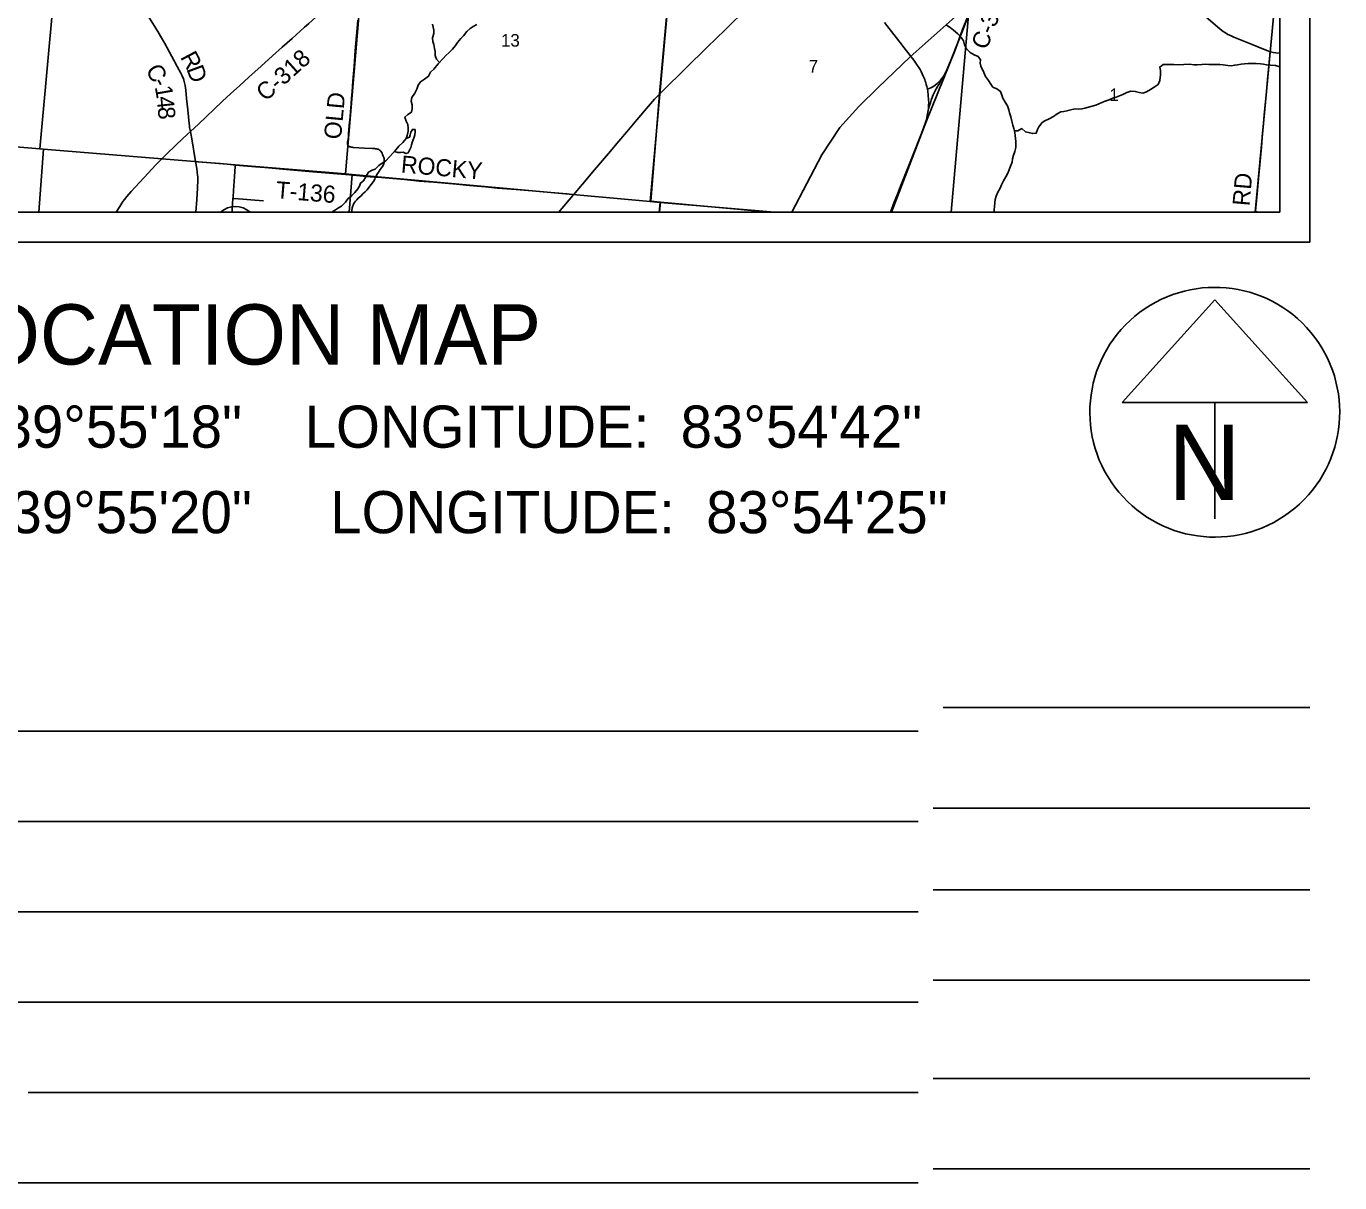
# Model space of a CAD drawing. Extents: x 0 to 34, y 0 to 22.
# Drawn here: x 4.739 to 9.099, y 10.877 to 14.717 of the extents above; entities that cross this region are included whole.
import ezdxf

# ---------------------------------------------------------------- set-up
doc = ezdxf.new("R2010")
doc.units = 0
for name, color, linetype in [('Default', 7, 'Continuous'), ('GM_X_City_Street', 7, 'Continuous'), ('GM_X_County_Road', 7, 'Continuous'), ('GM_X_County_Road_Text', 7, 'Continuous'), ('GM_X_Major_River_Text', 7, 'Continuous'), ('GM_X_Minor_Lake', 7, 'Continuous'), ('GM_X_Minor_River', 7, 'Continuous'), ('GM_X_Rail_Line', 7, 'Continuous'), ('GM_X_Section', 7, 'Continuous'), ('GM_X_Section_Text', 7, 'Continuous'), ('GM_X_Township_Road', 7, 'Continuous'), ('GM_X_Township_Road_Text', 7, 'Continuous'), ('GM_X_US_Route', 7, 'Continuous'), ('SH_Data', 7, 'Continuous'), ('SH_Text', 7, 'Continuous')]:
    doc.layers.add(name, color=color, linetype=linetype)

msp = doc.modelspace()

# ---------------------------------------------------------------- linework, layer by layer
at = {"layer": 'Default'}
for points in [[(7.2235, 14.1), (7.8093, 14.1), (7.893, 15.0559), (6.9002, 15.1449), (6.8099, 14.1356), (6.8432, 14.1321)], [(7.8093, 14.1), (8.8187, 14.1), (8.8988, 14.9496), (7.893, 15.0559)], [(8.8187, 14.1), (8.9, 14.1), (8.9, 14.9495), (8.8988, 14.9496)], [(3.7756, 14.1), (4.7807, 14.1), (4.7952, 14.3092), (4.7835, 14.3098), (3.8021, 14.3916)], [(4.7807, 14.1), (5.8111, 14.1), (5.8205, 14.2252), (5.7982, 14.227), (4.7952, 14.3092)], [(5.8111, 14.1), (6.8403, 14.1), (6.8432, 14.1321), (6.8099, 14.1356), (5.8205, 14.2252)], [(6.8403, 14.1), (7.2235, 14.1), (6.8432, 14.1321)]]:
    msp.add_lwpolyline(points, close=True, dxfattribs=at)
at = {"layer": 'GM_X_City_Street'}
for points in [[(6.9742, 15.9512), (6.8413, 14.4929), (6.8121, 14.1362), (6.8442, 14.1329), (7.2075, 14.1), (8.9, 14.1), (8.9, 20.0308)], [(2.1, 15.6775), (2.1, 14.1), (6.8413, 14.1), (6.8442, 14.1329), (6.8121, 14.1362), (6.8413, 14.4929), (6.9742, 15.9512)]]:
    msp.add_lwpolyline(points, dxfattribs=at)
msp.add_lwpolyline([(6.8413, 14.1), (7.2075, 14.1), (6.8442, 14.1329)], close=True, dxfattribs=at)
at = {"layer": 'GM_X_County_Road'}
msp.add_line((8.8195, 14.1), (8.8197, 14.1018), dxfattribs=at)
for points in [[(7.7781, 14.5434), (7.7795, 14.5452), (7.7848, 14.5528), (7.7895, 14.5608), (7.7937, 14.569), (7.7987, 14.5803), (7.8089, 14.6063), (7.8301, 14.6601), (7.8465, 14.702), (7.8702, 14.7628), (7.8835, 14.7975), (7.8982, 14.8352), (7.9084, 14.8612), (7.9276, 14.9103), (7.9492, 14.9652), (7.9593, 14.9913), (7.9806, 15.0463), (7.997, 15.0885)], [(5.2834, 14.3675), (5.3102, 14.3924), (5.3892, 14.4668), (5.4048, 14.4812), (5.4275, 14.5022), (5.4459, 14.519), (5.4779, 14.5483), (5.5181, 14.585), (5.5561, 14.6191), (5.5885, 14.6481), (5.6209, 14.6768), (5.6627, 14.7139), (5.6765, 14.7264), (5.6996, 14.7472), (5.7203, 14.766), (5.7783, 14.8176), (5.8131, 14.8486), (5.8434, 14.8753), (5.8549, 14.8856)], [(6.8408, 14.4917), (6.8415, 14.4924), (6.8505, 14.5014), (6.9283, 14.5774), (6.9993, 14.6471), (7.0594, 14.7056), (7.0838, 14.7296), (7.1082, 14.7535), (7.1173, 14.7619), (7.1221, 14.7656), (7.1247, 14.7672), (7.1302, 14.77), (7.1359, 14.7723), (7.1446, 14.7755), (7.1653, 14.7821), (7.192, 14.7905), (7.248, 14.8091), (7.3424, 14.8403), (7.3747, 14.8516), (7.4009, 14.8614), (7.4386, 14.8764)], [(5.2834, 14.3675), (5.2817, 14.3768), (5.2809, 14.3811), (5.2799, 14.387), (5.2791, 14.3933), (5.2745, 14.4397), (5.2709, 14.4768), (5.268, 14.5046), (5.2659, 14.5201), (5.2641, 14.5293), (5.2617, 14.5383), (5.2601, 14.5434), (5.2586, 14.5472), (5.2561, 14.553), (5.252, 14.5613), (5.24, 14.5832), (5.2296, 14.6022), (5.1983, 14.6594), (5.1845, 14.6838), (5.175, 14.6998), (5.1587, 14.7263), (5.1425, 14.7528), (5.1216, 14.7873), (5.1201, 14.7896)], [(8.6313, 14.7682), (8.7025, 14.7079), (8.7123, 14.7002), (8.7201, 14.6949), (8.7282, 14.6902), (8.7366, 14.6861), (8.7481, 14.6811), (8.8087, 14.6567), (8.8459, 14.6411), (8.8604, 14.6354), (8.8666, 14.6333), (8.8693, 14.6326)], [(8.8197, 14.1018), (8.8211, 14.1152), (8.8242, 14.1493), (8.8264, 14.1741), (8.8273, 14.1865), (8.8282, 14.1988), (8.8305, 14.2236), (8.8317, 14.236), (8.8326, 14.2452), (8.8347, 14.2691), (8.838, 14.3048), (8.8402, 14.3295), (8.8423, 14.3512), (8.8464, 14.3946), (8.849, 14.4224), (8.8529, 14.4658), (8.8559, 14.4998), (8.8594, 14.5401), (8.8626, 14.5741), (8.8672, 14.6209), (8.8677, 14.6249), (8.8681, 14.6281), (8.8693, 14.6326)], [(8.8693, 14.6326), (8.8737, 14.6314), (8.8785, 14.6303), (8.8877, 14.6288), (8.9, 14.6272)], [(7.7305, 14.508), (7.7362, 14.5101), (7.742, 14.5127), (7.7481, 14.516), (7.7556, 14.5214), (7.7628, 14.5272), (7.7695, 14.5335), (7.7737, 14.538), (7.7781, 14.5434)], [(7.7337, 14.4429), (7.7374, 14.4537), (7.7402, 14.4624), (7.743, 14.4718), (7.747, 14.4836), (7.7495, 14.4899), (7.7514, 14.4943), (7.7545, 14.5002), (7.76, 14.5094), (7.7715, 14.5295), (7.7743, 14.5351), (7.7781, 14.5434)], [(6.5556, 14.1575), (6.5853, 14.1927), (6.6254, 14.2402), (6.6714, 14.295), (6.7057, 14.3351), (6.7378, 14.3731), (6.7659, 14.4063), (6.8042, 14.4512), (6.8246, 14.4747), (6.8352, 14.486), (6.8408, 14.4917)], [(5.0372, 14.1), (5.0488, 14.1188), (5.0588, 14.1346), (5.0643, 14.1422), (5.0723, 14.1518), (5.0868, 14.1679), (5.1436, 14.2297), (5.1688, 14.2572), (5.1839, 14.2729), (5.2017, 14.2902), (5.2378, 14.3244), (5.2738, 14.3586), (5.2834, 14.3675)], [(5.3005, 14.268), (5.2879, 14.3429), (5.2847, 14.3607), (5.2834, 14.3675)], [(5.302, 14.1), (5.3046, 14.1416), (5.3066, 14.1789), (5.3077, 14.2069), (5.3076, 14.2163), (5.3062, 14.2318), (5.3045, 14.2442), (5.3005, 14.268)], [(6.5072, 14.1), (6.5112, 14.1048), (6.5533, 14.1547), (6.5556, 14.1575)]]:
    msp.add_lwpolyline(points, dxfattribs=at)
at = {"layer": 'GM_X_Major_River_Text'}
msp.add_line((5.3836, 14.1), (5.4815, 14.1), dxfattribs=at)
msp.add_arc((5.4326, 14.0439), 0.0744, 48.835, 131.165, dxfattribs=at)
at = {"layer": 'GM_X_Minor_Lake'}
for points in [[(5.9607, 14.3015), (5.9719, 14.298), (5.981, 14.2983), (5.9897, 14.2989), (5.9984, 14.295), (6.0059, 14.2972), (6.0106, 14.3058), (6.0148, 14.3141), (6.0172, 14.3232), (6.02, 14.3315), (6.0231, 14.3398), (6.0262, 14.3489), (6.0282, 14.3568), (6.0298, 14.3662), (6.0292, 14.3742), (6.0205, 14.3743), (6.0151, 14.3653), (6.0127, 14.3562), (6.0111, 14.3487), (5.9993, 14.3443)], [(5.9993, 14.3443), (5.9886, 14.3307), (5.9752, 14.3188), (5.9607, 14.3015)]]:
    msp.add_lwpolyline(points, dxfattribs=at)
at = {"layer": 'GM_X_Minor_River'}
for points in [[(6.1103, 14.5966), (6.1009, 14.6076), (6.0965, 14.6205), (6.0959, 14.6334), (6.0942, 14.6433), (6.0917, 14.6566), (6.0887, 14.6665), (6.087, 14.6791), (6.0913, 14.6927), (6.0922, 14.7045), (6.0897, 14.7144), (6.0868, 14.7239)], [(6.106, 14.5919), (6.1223, 14.6096), (6.1315, 14.6202), (6.141, 14.6292), (6.1532, 14.6405), (6.1639, 14.6537), (6.1704, 14.6635), (6.1811, 14.6767), (6.1906, 14.685), (6.2013, 14.6993), (6.2124, 14.7094), (6.2219, 14.7158), (6.234, 14.7233)], [(7.7933, 14.7202), (7.8054, 14.7125), (7.8174, 14.7041), (7.8309, 14.6922), (7.8426, 14.68), (7.8497, 14.6686), (7.853, 14.6553), (7.8601, 14.642), (7.8728, 14.6301), (7.8856, 14.622), (7.8985, 14.617), (7.9071, 14.606), (7.9059, 14.595), (7.9077, 14.5851), (7.9177, 14.564)], [(6.0478, 14.5324), (6.0607, 14.5413), (6.0741, 14.551), (6.0807, 14.5642), (6.0914, 14.575), (6.106, 14.5919)], [(8.5048, 14.5554), (8.5041, 14.5697), (8.5016, 14.5815), (8.513, 14.5901), (8.5485, 14.5898), (8.5637, 14.5886), (8.5815, 14.59), (8.5989, 14.5913), (8.6159, 14.5889), (8.6261, 14.5885), (8.6412, 14.5899), (8.6541, 14.5913), (8.6651, 14.5905), (8.6756, 14.5896), (8.6893, 14.5899), (8.7018, 14.5906), (8.7127, 14.589), (8.7275, 14.5866), (8.7403, 14.5861), (8.7502, 14.5875), (8.7604, 14.5894), (8.7721, 14.5912), (8.7827, 14.5918), (8.7952, 14.5929), (8.81, 14.5931), (8.8217, 14.5931), (8.8364, 14.5926), (8.8466, 14.591), (8.8565, 14.589), (8.8693, 14.5874), (8.8856, 14.5869), (8.8973, 14.583), (8.9, 14.5818)], [(5.7528, 14.1), (5.7621, 14.1058), (5.7754, 14.1143), (5.7849, 14.1191), (5.7983, 14.1334), (5.806, 14.1435), (5.8197, 14.1555), (5.8297, 14.1652), (5.8393, 14.1768), (5.8451, 14.1866), (5.8482, 14.1964), (5.8578, 14.2039), (5.8655, 14.2171), (5.8751, 14.2329), (5.8873, 14.2391), (5.8972, 14.2428), (5.9094, 14.2548), (5.9197, 14.2622), (5.9327, 14.2704), (5.9442, 14.2839), (5.9568, 14.2963), (5.9607, 14.3015), (5.9752, 14.3188), (5.9886, 14.3307), (5.9993, 14.3443), (6.0029, 14.3544), (6.0061, 14.3692), (6.0066, 14.379), (6.0052, 14.3912), (6.0001, 14.4022), (5.9949, 14.4152), (6.0049, 14.4241), (6.0171, 14.4323), (6.0202, 14.4425), (6.02, 14.4558), (6.0167, 14.4679), (6.0184, 14.4804), (6.0288, 14.4951), (6.0354, 14.5083), (6.0393, 14.5219), (6.0478, 14.5324)], [(7.9177, 14.564), (7.9238, 14.55), (7.9335, 14.537), (7.9414, 14.5251), (7.9477, 14.5152), (7.9613, 14.5094), (7.9729, 14.5009), (7.977, 14.488), (7.9807, 14.4785), (7.9889, 14.4655), (7.996, 14.4525), (8.0004, 14.4396), (8.0029, 14.4297), (8.0073, 14.4163), (8.011, 14.4023), (8.0139, 14.3886), (8.0168, 14.3772), (8.0201, 14.3646), (8.0215, 14.354), (8.0226, 14.3441), (8.0236, 14.3339), (8.0243, 14.3244), (8.0238, 14.3149), (8.0202, 14.3016), (8.0163, 14.2895), (8.0132, 14.2763), (8.0116, 14.2661), (8.0065, 14.2521), (8.0015, 14.2404), (7.996, 14.2271), (7.9903, 14.2173), (7.9829, 14.2041), (7.9768, 14.1905), (7.9717, 14.1796), (7.9644, 14.1656), (7.9582, 14.1524), (7.9558, 14.1422), (7.9538, 14.1323), (7.9526, 14.1179), (7.9521, 14.1085), (7.9516, 14.1)], [(8.0187, 14.3701), (8.0308, 14.3702), (8.0437, 14.3773), (8.0565, 14.3665), (8.0705, 14.3634), (8.0803, 14.3606), (8.092, 14.3616), (8.0959, 14.3737), (8.1006, 14.3835), (8.1109, 14.3971), (8.1205, 14.4031), (8.1349, 14.4097), (8.1486, 14.4176), (8.1612, 14.4266), (8.1738, 14.4325), (8.1832, 14.4335), (8.1935, 14.4357), (8.2064, 14.4394), (8.2208, 14.4426), (8.2322, 14.4422), (8.2432, 14.4428), (8.2534, 14.445), (8.2648, 14.4483), (8.277, 14.4512), (8.2891, 14.4549), (8.2994, 14.4597), (8.3093, 14.4641), (8.3207, 14.4682), (8.334, 14.4726), (8.3462, 14.4786), (8.3572, 14.4819), (8.3686, 14.4855), (8.3792, 14.4904), (8.3929, 14.4971), (8.4055, 14.5015), (8.4202, 14.5009), (8.4335, 14.4974), (8.4456, 14.495), (8.4581, 14.4998), (8.4711, 14.5076), (8.4836, 14.5143), (8.4962, 14.5237), (8.502, 14.5369), (8.5048, 14.5554)]]:
    msp.add_lwpolyline(points, dxfattribs=at)
at = {"layer": 'GM_X_Rail_Line'}
for points in [[(7.2798, 14.1), (7.3804, 14.2899), (7.4399, 14.3809), (7.5029, 14.451), (7.5671, 14.514), (7.6729, 14.6161), (7.8627, 14.7836), (7.9234, 14.8447), (7.9746, 14.9008), (8.0463, 14.9864), (8.1054, 15.083), (8.1652, 15.2252), (8.1826, 15.274), (8.2135, 15.3861), (8.2835, 15.6324), (8.3606, 15.9006), (8.4204, 16.0285), (8.4785, 16.1527), (8.5411, 16.2834), (8.5955, 16.4012), (8.7466, 16.719), (8.8431, 16.9243), (8.9, 17.0477)], [(8.6715, 16.5448), (8.4316, 16.0366), (8.3713, 15.9072), (8.1815, 15.2486), (8.1107, 15.0795), (8.0486, 14.9789), (7.9789, 14.8968), (7.9015, 14.815), (7.882, 14.794), (7.8474, 14.7064), (7.8234, 14.6409), (7.725, 14.3971), (7.6108, 14.1)]]:
    msp.add_lwpolyline(points, dxfattribs=at)
at = {"layer": 'GM_X_Section'}
for points in [[(3.89, 15.3957), (4.8743, 15.3051), (4.7835, 14.3098), (3.8021, 14.3916), (3.7885, 14.3929)], [(4.8743, 15.3051), (5.8825, 15.2209), (5.7982, 14.227), (4.7952, 14.3092), (4.7835, 14.3098)], [(5.8825, 15.2209), (6.9002, 15.1449), (6.8099, 14.1356), (5.8205, 14.2252), (5.7982, 14.227)]]:
    msp.add_lwpolyline(points, close=True, dxfattribs=at)
at = {"layer": 'GM_X_Township_Road'}
for points in [[(5.8984, 14.2159), (5.8994, 14.2185), (5.901, 14.2215), (5.9029, 14.2249), (5.9057, 14.2294), (5.9101, 14.2358), (5.914, 14.2413), (5.9207, 14.251), (5.9231, 14.2549), (5.9249, 14.2582), (5.9258, 14.2608), (5.9265, 14.2633), (5.9271, 14.2662), (5.9272, 14.2696), (5.9272, 14.2725), (5.9269, 14.276), (5.9265, 14.2782), (5.9255, 14.2817), (5.9239, 14.286), (5.9217, 14.2912), (5.9198, 14.2953), (5.9176, 14.2992), (5.9157, 14.3018), (5.9138, 14.304), (5.9117, 14.3058), (5.9092, 14.3074), (5.9066, 14.3085), (5.9041, 14.3092), (5.9011, 14.3099), (5.8983, 14.3103), (5.8951, 14.3107), (5.8879, 14.311), (5.8611, 14.3122), (5.8238, 14.3148), (5.8205, 14.3151), (5.8171, 14.3156), (5.8145, 14.3163), (5.8127, 14.3171), (5.8105, 14.3182), (5.8091, 14.3192), (5.8077, 14.3204), (5.8065, 14.3218), (5.8058, 14.3229), (5.8051, 14.3243), (5.8047, 14.3256), (5.8045, 14.3275), (5.8047, 14.3293), (5.8053, 14.3325), (5.8062, 14.3373), (5.8069, 14.3419), (5.8079, 14.3509), (5.8088, 14.3604), (5.811, 14.3875), (5.8135, 14.4165), (5.8149, 14.4331), (5.817, 14.4599), (5.8186, 14.4784), (5.82, 14.5003), (5.8226, 14.5343), (5.8268, 14.5837), (5.831, 14.6362), (5.8373, 14.7104), (5.8396, 14.7375)], [(5.3005, 14.268), (5.3085, 14.2674), (5.3517, 14.2638), (5.3825, 14.2609), (5.4164, 14.2577), (5.433, 14.2562)], [(5.4248, 14.1449), (5.4251, 14.1494), (5.4266, 14.1713), (5.4299, 14.2178), (5.4326, 14.2519), (5.433, 14.2562)], [(5.433, 14.2562), (5.4996, 14.2504), (5.5302, 14.2478), (5.5423, 14.2468), (5.5908, 14.2425), (5.6771, 14.2353), (5.8121, 14.2234), (5.88, 14.2174), (5.8984, 14.2159)], [(5.8186, 14.1), (5.819, 14.1038), (5.8208, 14.1144), (5.8224, 14.1205), (5.8234, 14.1235), (5.8246, 14.1264), (5.8261, 14.1289), (5.8281, 14.1321), (5.8321, 14.1368), (5.8359, 14.1412), (5.8409, 14.146), (5.8489, 14.1533), (5.8563, 14.1602), (5.8638, 14.1675), (5.8699, 14.1743), (5.8761, 14.1816), (5.8837, 14.1917), (5.891, 14.2019), (5.8954, 14.2088), (5.8974, 14.2134), (5.8984, 14.2159)], [(5.8984, 14.2159), (5.9047, 14.2154), (5.9942, 14.2078), (6.0251, 14.2047), (6.0431, 14.2032), (6.0913, 14.1991), (6.1673, 14.1923), (6.2104, 14.1883), (6.2352, 14.1862), (6.263, 14.1836), (6.3032, 14.1799), (6.365, 14.1747), (6.4176, 14.1704), (6.4544, 14.1672), (6.5068, 14.1625), (6.5346, 14.1601), (6.5425, 14.1593), (6.5523, 14.1579), (6.5556, 14.1575)], [(5.422, 14.1), (5.4226, 14.1092), (5.4248, 14.1449)], [(5.4248, 14.1449), (5.4273, 14.1448), (5.4573, 14.1428), (5.4979, 14.1399), (5.5261, 14.1377)], [(8.8197, 14.1018), (8.8247, 14.1012), (8.8362, 14.1)]]:
    msp.add_lwpolyline(points, dxfattribs=at)
at = {"layer": 'GM_X_US_Route'}
for points in [[(7.7337, 14.4429), (7.7344, 14.4545), (7.7347, 14.4639), (7.7344, 14.4732), (7.7331, 14.4888), (7.7316, 14.5012), (7.7305, 14.508), (7.7287, 14.5168), (7.7267, 14.5241), (7.7246, 14.5308), (7.7231, 14.5351), (7.7214, 14.5401), (7.7177, 14.549), (7.7131, 14.5589), (7.7094, 14.5665), (7.7058, 14.5732), (7.7017, 14.5803), (7.6943, 14.5914), (7.685, 14.6046), (7.6733, 14.6197), (7.6534, 14.6454), (7.6391, 14.6638), (7.6115, 14.6995), (7.588, 14.7295)], [(7.7042, 14.3446), (7.7109, 14.3613), (7.7186, 14.3816), (7.7232, 14.3944), (7.7262, 14.404), (7.7285, 14.4129), (7.7301, 14.4205), (7.7319, 14.4308), (7.7331, 14.4389), (7.7337, 14.4429)], [(7.6076, 14.1), (7.6202, 14.1331), (7.6306, 14.159), (7.64, 14.183), (7.6464, 14.1993), (7.6706, 14.2602), (7.7042, 14.3446)]]:
    msp.add_lwpolyline(points, dxfattribs=at)
at = {"layer": 'SH_Data'}
for p, q in [((9, 21), (9, 14)), ((8.9, 20.9), (8.9, 14.1)), ((2.1, 14.1), (8.9, 14.1)), ((2, 14), (9, 14)), ((8.6845, 13.809), (8.3769, 13.4678)), ((8.9921, 13.4678), (8.6845, 13.809)), ((8.3769, 13.4678), (8.9921, 13.4678)), ((8.6845, 13.4678), (8.6845, 13.081)), ((8.6845, 13.4353), (8.6845, 13.4353)), ((8.6845, 13.4353), (8.6845, 13.4353)), ((7.7827, 12.4553), (9, 12.4553)), ((7.7, 12.3767), (4.4937, 12.3767)), ((9, 12.1207), (7.75, 12.1207)), ((7.7, 12.0767), (3.9895, 12.0767)), ((9, 11.8491), (7.75, 11.8491)), ((7.7, 11.7767), (3.6192, 11.7767)), ((9, 11.5491), (7.75, 11.5491)), ((7.7, 11.4767), (3.3288, 11.4767)), ((9, 11.2223), (7.75, 11.2223)), ((7.7, 11.1767), (4.7452, 11.1767)), ((9, 10.9223), (7.75, 10.9223)), ((7.7, 10.8767), (3.3604, 10.8767))]:
    msp.add_line(p, q, dxfattribs=at)
msp.add_arc((8.6845, 13.4353), 0.4148, 129.7798, 129.7633, dxfattribs=at)

# ---------------------------------------------------------------- texts
at = {"layer": 'GM_X_County_Road_Text'}
for s, height, rotation, p in [('C-338', 0.05682, 68.9618, (7.927, 14.636)), ('R', 0.0568, 297.9607, (5.2486, 14.6149)), ('C-318', 0.05682, 41.9057, (5.5331, 14.4651)), ('C', 0.0568, 298.2532, (5.1335, 14.5728)), ('D', 0.0568, 290.2461, (5.2697, 14.5755)), ('-', 0.0568, 298.276, (5.1556, 14.5317)), ('1', 0.0568, 279.7682, (5.1651, 14.5157)), ('4', 0.0568, 275.8124, (5.1709, 14.4822)), ('8', 0.0568, 275.6345, (5.1744, 14.4474)), ('RD', 0.05682, 85.1103, (8.7998, 14.1186))]:
    msp.add_text(s, height=height, rotation=rotation, dxfattribs=at).set_placement(p)
at = {"layer": 'GM_X_Section_Text'}
for s, height, p in [('13', 0.04186, (6.3147, 14.6494)), ('7', 0.0419, (7.3364, 14.5633)), ('1', 0.0419, (8.3347, 14.4686))]:
    msp.add_text(s, height=height, rotation=0, dxfattribs=at).set_placement(p)
at = {"layer": 'GM_X_Township_Road_Text'}
for s, rotation, p in [('OLD', 84.7464, (5.7833, 14.3399)), ('ROCKY', 354.9449, (5.981, 14.2316)), ('T-136', 355.2365, (5.5652, 14.1461))]:
    msp.add_text(s, height=0.05682, rotation=rotation, dxfattribs=at).set_placement(p)
at = {"layer": 'SH_Data'}
msp.add_text('N', height=0.25, dxfattribs=at).set_placement((8.5292, 13.1439))
at = {"layer": 'SH_Text'}
for s, height, p in [('LOCATION MAP', 0.2, (4.4269, 13.5937)), ('CLA-40-0732    LATITUDE:  39°55\'18"    LONGITUDE:  83°54\'42"', 0.14, (2.2704, 13.3175)), ('CLA-40-0757     LATITUDE:  39°55\'20"     LONGITUDE:  83°54\'25"', 0.14, (2.2512, 13.0335))]:
    msp.add_text(s, height=height, dxfattribs=at).set_placement(p)

doc.saveas('drawing.dxf')
